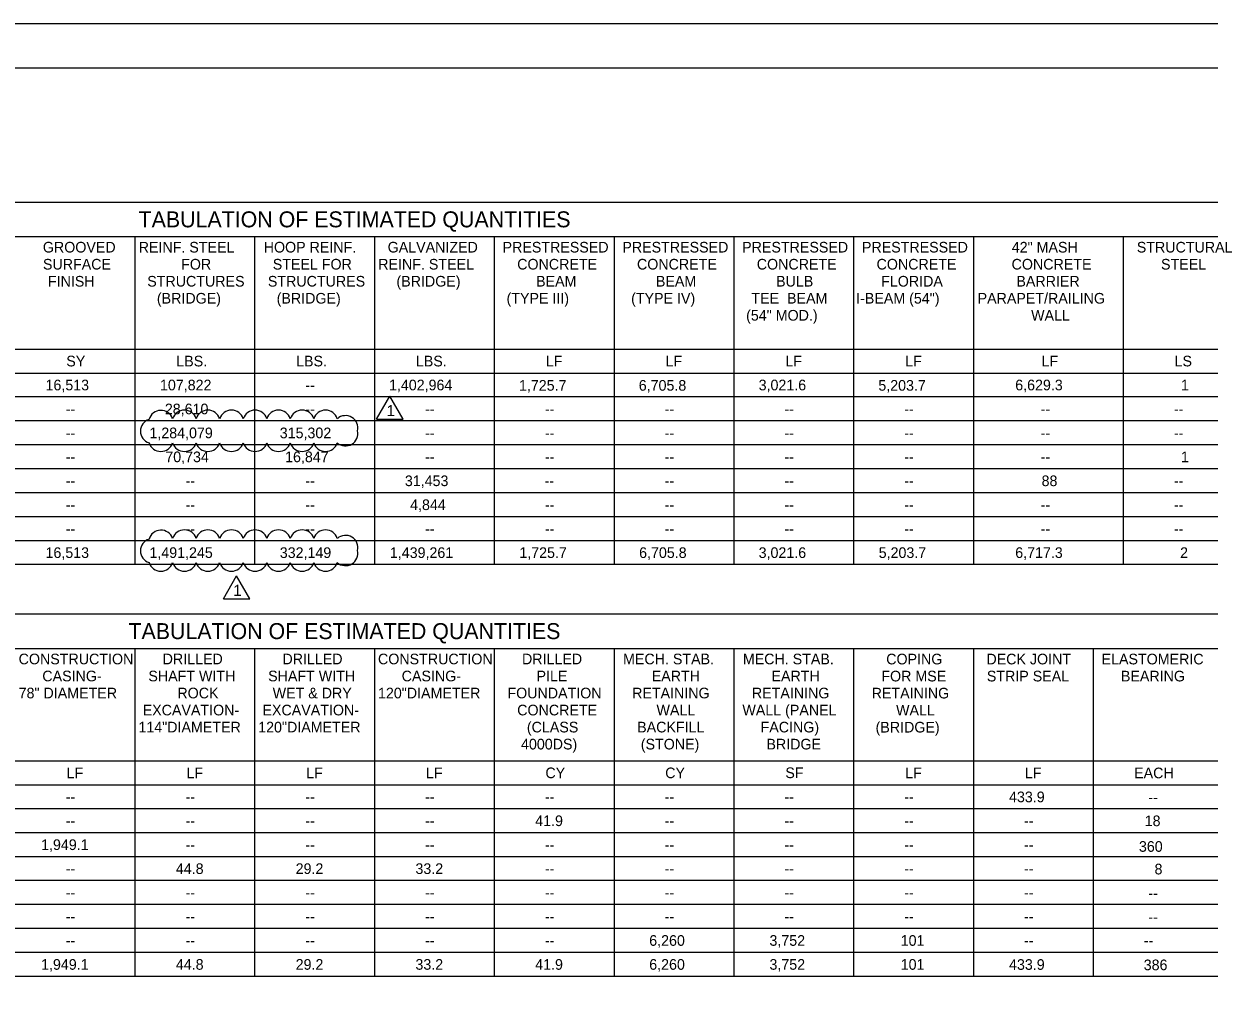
# Model space of a CAD drawing. Extents: x -125.5 to -89.4, y -5.1 to 16.9.
# Drawn here: x -111.65 to -98.29, y 5.93 to 16.93 of the extents above; entities that cross this region are included whole.
import ezdxf

# ---------------------------------------------------------------- set-up
doc = ezdxf.new("R2010")
doc.units = 0
for name, color, linetype in [('BR_BORDER LINES', 7, 'Continuous'), ('BR_TABLE LINES', 7, 'Continuous'), ('BR_TEXT', 7, 'Continuous'), ('Level 31', 7, 'Continuous')]:
    doc.layers.add(name, color=color, linetype=linetype)

msp = doc.modelspace()

# ---------------------------------------------------------------- linework, layer by layer
at = {"layer": 'BR_BORDER LINES'}
msp.add_line((-90.033, 16.434), (-123.699, 16.434), dxfattribs=at)
at = {"layer": 'BR_TABLE LINES'}
for p, q in [((-123.551, 14.923), (-90.138, 14.923)), ((-123.551, 14.533), (-90.138, 14.533)), ((-110.401, 14.533), (-110.401, 10.835)), ((-109.051, 14.533), (-109.051, 10.835)), ((-107.701, 14.533), (-107.701, 10.835)), ((-106.351, 14.533), (-106.351, 10.835)), ((-105.001, 14.533), (-105.001, 10.835)), ((-103.651, 14.533), (-103.651, 10.835)), ((-102.301, 14.533), (-102.301, 10.835)), ((-100.951, 14.533), (-100.951, 10.835)), ((-99.261, 14.533), (-99.261, 10.835)), ((-123.551, 13.265), (-90.138, 13.265)), ((-123.551, 12.995), (-90.138, 12.995)), ((-90.138, 12.725), (-123.551, 12.725)), ((-90.138, 12.455), (-123.551, 12.455)), ((-90.138, 12.185), (-123.551, 12.185)), ((-90.138, 11.915), (-123.551, 11.915)), ((-90.138, 11.645), (-123.551, 11.645)), ((-90.138, 11.375), (-123.551, 11.375)), ((-90.138, 11.105), (-123.551, 11.105)), ((-90.138, 10.835), (-123.551, 10.835)), ((-123.551, 10.28), (-91.389, 10.28)), ((-123.551, 9.89), (-91.389, 9.89)), ((-110.401, 9.89), (-110.401, 6.192)), ((-109.051, 9.89), (-109.051, 6.192)), ((-107.701, 9.89), (-107.701, 6.192)), ((-106.351, 9.89), (-106.351, 6.192)), ((-105.001, 9.89), (-105.001, 6.192)), ((-103.651, 9.89), (-103.651, 6.192)), ((-102.301, 9.889), (-102.301, 6.192)), ((-100.951, 9.889), (-100.951, 6.192)), ((-99.601, 9.889), (-99.601, 6.192)), ((-123.551, 8.622), (-91.389, 8.622)), ((-123.551, 8.352), (-91.389, 8.352)), ((-91.389, 8.082), (-123.551, 8.082)), ((-91.389, 7.812), (-123.551, 7.812)), ((-91.389, 7.542), (-123.551, 7.542)), ((-91.389, 7.272), (-123.551, 7.272)), ((-91.389, 7.002), (-123.551, 7.002)), ((-91.389, 6.732), (-123.551, 6.732)), ((-91.389, 6.462), (-123.551, 6.462)), ((-91.389, 6.192), (-123.551, 6.192))]:
    msp.add_line(p, q, dxfattribs=at)
at = {"layer": 'BR_TEXT'}
for p, q in [((-107.676, 12.475), (-107.526, 12.735)), ((-107.376, 12.475), (-107.526, 12.735)), ((-107.676, 12.475), (-107.376, 12.475)), ((-109.404, 10.449), (-109.254, 10.709)), ((-109.104, 10.449), (-109.254, 10.709)), ((-109.404, 10.449), (-109.104, 10.449))]:
    msp.add_line(p, q, dxfattribs=at)
for centre, start, end in [((-110.107, 12.435), 19.0694, 164.0694), ((-109.843, 12.438), 17.5, 162.5), ((-109.578, 12.438), 17.5, 162.5), ((-109.312, 12.438), 17.5, 162.5), ((-109.047, 12.438), 17.5, 162.5), ((-108.782, 12.438), 17.5, 162.5), ((-108.517, 12.438), 17.5, 162.5), ((-108.252, 12.438), 17.5, 162.5), ((-110.199, 12.34), 107.5, 252.5), ((-108.027, 12.376), 346.5605, 131.5605), ((-108.027, 12.312), 228.3256, 13.3256), ((-110.108, 12.25), 197.5, 342.5), ((-109.843, 12.25), 197.5, 342.5), ((-109.578, 12.25), 197.5, 342.5), ((-109.313, 12.25), 197.5, 342.5), ((-109.047, 12.25), 197.5, 342.5), ((-108.782, 12.25), 197.5, 342.5), ((-108.517, 12.25), 197.5, 342.5), ((-108.252, 12.25), 197.5, 342.5), ((-109.843, 11.088), 17.5, 162.5), ((-109.578, 11.088), 17.5, 162.5), ((-109.312, 11.088), 17.5, 162.5), ((-109.047, 11.088), 17.5, 162.5), ((-108.782, 11.088), 17.5, 162.5), ((-108.517, 11.088), 17.5, 162.5), ((-108.252, 11.088), 17.5, 162.5), ((-110.199, 10.99), 107.5, 252.5), ((-110.107, 11.085), 19.0694, 164.0694), ((-108.027, 11.026), 346.5605, 131.5605), ((-108.027, 10.962), 228.3256, 13.3256), ((-110.108, 10.9), 197.5, 342.5), ((-109.843, 10.9), 197.5, 342.5), ((-109.578, 10.9), 197.5, 342.5), ((-109.313, 10.9), 197.5, 342.5), ((-109.047, 10.9), 197.5, 342.5), ((-108.782, 10.9), 197.5, 342.5), ((-108.517, 10.9), 197.5, 342.5), ((-108.252, 10.9), 197.5, 342.5)]:
    msp.add_arc(centre, 0.139, start, end, dxfattribs=at)
at = {"layer": 'Level 31'}
msp.add_lwpolyline([(-125.533, -5.066), (-89.533, -5.066), (-89.533, 16.934), (-125.533, 16.934)], close=True, dxfattribs=at)

# ---------------------------------------------------------------- texts
at = {"layer": 'BR_TEXT'}
for s, height, p in [('TABULATION OF ESTIMATED QUANTITIES', 0.18, (-110.359, 14.638)), ('GROOVED ', 0.12, (-111.438, 14.354)), ('REINF. STEEL', 0.12, (-110.358, 14.354)), ('HOOP REINF. ', 0.12, (-108.949, 14.354)), ('GALVANIZED ', 0.12, (-107.552, 14.354)), ('PRESTRESSED ', 0.12, (-106.257, 14.354)), ('PRESTRESSED ', 0.12, (-104.907, 14.354)), ('PRESTRESSED ', 0.12, (-103.557, 14.354)), ('PRESTRESSED ', 0.12, (-102.207, 14.354)), ('42" MASH ', 0.12, (-100.518, 14.354)), ('STRUCTURAL ', 0.12, (-99.109, 14.354)), ('SURFACE ', 0.12, (-111.437, 14.162)), (' FOR', 0.12, (-109.924, 14.162)), ('STEEL FOR ', 0.12, (-108.847, 14.162)), ('REINF. STEEL ', 0.12, (-107.658, 14.162)), ('CONCRETE ', 0.12, (-106.092, 14.162)), ('CONCRETE ', 0.12, (-104.742, 14.162)), ('CONCRETE ', 0.12, (-103.392, 14.162)), ('CONCRETE', 0.12, (-102.042, 14.162)), ('CONCRETE ', 0.12, (-100.52, 14.162)), ('STEEL', 0.12, (-98.836, 14.162)), ('FINISH', 0.12, (-111.381, 13.97)), (' STRUCTURES ', 0.12, (-110.306, 13.97)), ('STRUCTURES ', 0.12, (-108.902, 13.97)), ('(BRIDGE)', 0.12, (-107.453, 13.97)), ('BEAM ', 0.12, (-105.879, 13.97)), ('BEAM ', 0.12, (-104.529, 13.97)), ('BULB ', 0.12, (-103.174, 13.97)), ('FLORIDA', 0.12, (-101.99, 13.97)), ('BARRIER ', 0.12, (-100.466, 13.97)), ('(BRIDGE)', 0.12, (-110.153, 13.778)), ('(BRIDGE)', 0.12, (-108.803, 13.778)), ('(TYPE III)', 0.12, (-106.212, 13.778)), ('(TYPE IV)', 0.12, (-104.808, 13.778)), ('TEE  BEAM ', 0.12, (-103.452, 13.778)), ('I-BEAM (54")', 0.12, (-102.272, 13.778)), ('PARAPET/RAILING ', 0.12, (-100.903, 13.778)), ('(54" MOD.)', 0.12, (-103.512, 13.586)), ('WALL', 0.12, (-100.3, 13.586)), ('SY', 0.12, (-111.174, 13.07)), ('LBS.', 0.12, (-109.934, 13.07)), ('LBS.', 0.12, (-108.584, 13.07)), ('LBS.', 0.12, (-107.234, 13.07)), ('LF', 0.12, (-105.77, 13.07)), ('LF', 0.12, (-104.42, 13.07)), ('LF', 0.12, (-103.07, 13.07)), ('LF', 0.12, (-101.72, 13.07)), ('LF', 0.12, (-100.182, 13.07)), ('LS', 0.12, (-98.683, 13.07)), ('16,513', 0.12, (-111.408, 12.8)), ('107,822', 0.12, (-110.118, 12.8)), ('--', 0.12, (-108.48, 12.8)), ('1,402,964', 0.12, (-107.537, 12.8)), ('1,725.7', 0.12, (-106.072, 12.796)), ('6,705.8', 0.12, (-104.722, 12.796)), ('3,021.6', 0.12, (-103.371, 12.8)), ('5,203.7', 0.12, (-102.022, 12.796)), ('6,629.3', 0.12, (-100.479, 12.8)), ('1', 0.12, (-98.611, 12.8)), ('--', 0.12, (-111.18, 12.53)), ('28,610', 0.12, (-110.063, 12.53)), ('--', 0.12, (-108.48, 12.53)), ('--', 0.12, (-107.13, 12.53)), ('--', 0.12, (-105.78, 12.53)), ('--', 0.12, (-104.43, 12.53)), ('--', 0.12, (-103.08, 12.53)), ('--', 0.12, (-101.73, 12.53)), ('--', 0.12, (-100.192, 12.53)), ('--', 0.12, (-98.69, 12.53)), ('--', 0.12, (-111.18, 12.26)), ('1,284,079', 0.12, (-110.237, 12.26)), ('315,302', 0.12, (-108.768, 12.26)), ('--', 0.12, (-107.13, 12.26)), ('--', 0.12, (-105.78, 12.26)), ('--', 0.12, (-104.43, 12.26)), ('--', 0.12, (-103.08, 12.26)), ('--', 0.12, (-101.73, 12.26)), ('--', 0.12, (-100.192, 12.26)), ('--', 0.12, (-98.69, 12.26)), ('--', 0.12, (-111.18, 11.99)), ('70,734', 0.12, (-110.058, 11.99)), ('16,847', 0.12, (-108.708, 11.99)), ('--', 0.12, (-107.13, 11.99)), ('--', 0.12, (-105.78, 11.99)), ('--', 0.12, (-104.43, 11.99)), ('--', 0.12, (-103.08, 11.99)), ('--', 0.12, (-101.73, 11.99)), ('--', 0.12, (-100.192, 11.99)), ('1', 0.12, (-98.611, 11.99)), ('--', 0.12, (-111.18, 11.72)), ('--', 0.12, (-109.83, 11.72)), ('--', 0.12, (-108.48, 11.72)), ('31,453', 0.12, (-107.358, 11.72)), ('--', 0.12, (-105.783, 11.721)), ('--', 0.12, (-104.43, 11.72)), ('--', 0.12, (-103.08, 11.72)), ('--', 0.12, (-101.73, 11.72)), ('88', 0.12, (-100.182, 11.72)), ('--', 0.12, (-98.69, 11.72)), ('--', 0.12, (-111.18, 11.45)), ('--', 0.12, (-109.83, 11.45)), ('--', 0.12, (-108.48, 11.45)), ('4,844', 0.12, (-107.299, 11.45)), ('--', 0.12, (-105.78, 11.45)), ('--', 0.12, (-104.43, 11.45)), ('--', 0.12, (-103.08, 11.45)), ('--', 0.12, (-101.73, 11.45)), ('--', 0.12, (-100.192, 11.45)), ('--', 0.12, (-98.69, 11.45)), ('--', 0.12, (-111.18, 11.18)), ('--', 0.12, (-109.83, 11.18)), ('--', 0.12, (-108.48, 11.18)), ('--', 0.12, (-107.13, 11.18)), ('--', 0.12, (-105.78, 11.18)), ('--', 0.12, (-104.43, 11.18)), ('--', 0.12, (-103.08, 11.18)), ('--', 0.12, (-101.73, 11.18)), ('--', 0.12, (-100.192, 11.18)), ('--', 0.12, (-98.69, 11.18)), ('16,513', 0.12, (-111.408, 10.91)), ('1,491,245', 0.12, (-110.237, 10.91)), ('332,149', 0.12, (-108.768, 10.91)), ('1,439,261', 0.12, (-107.527, 10.91)), ('1,725.7', 0.12, (-106.068, 10.91)), ('6,705.8', 0.12, (-104.718, 10.91)), ('3,021.6', 0.12, (-103.371, 10.91)), ('5,203.7', 0.12, (-102.018, 10.91)), ('6,717.3', 0.12, (-100.479, 10.91)), ('2', 0.12, (-98.621, 10.91)), ('TABULATION OF ESTIMATED QUANTITIES', 0.18, (-110.473, 9.995)), ('CONSTRUCTION ', 0.12, (-111.711, 9.711)), ('DRILLED ', 0.12, (-110.088, 9.711)), ('DRILLED ', 0.12, (-108.738, 9.711)), ('CONSTRUCTION ', 0.12, (-107.661, 9.711)), ('DRILLED ', 0.12, (-106.038, 9.711)), ('MECH. STAB. ', 0.12, (-104.899, 9.711)), ('MECH. STAB. ', 0.12, (-103.549, 9.711)), ('COPING ', 0.12, (-101.933, 9.71)), ('DECK JOINT ', 0.12, (-100.804, 9.71)), ('ELASTOMERIC ', 0.12, (-99.506, 9.71)), ('CASING- ', 0.12, (-111.444, 9.519)), ('SHAFT WITH ', 0.12, (-110.249, 9.519)), ('SHAFT WITH ', 0.12, (-108.899, 9.519)), ('CASING- ', 0.12, (-107.394, 9.519)), ('PILE ', 0.12, (-105.874, 9.519)), ('EARTH ', 0.12, (-104.576, 9.519)), ('EARTH ', 0.12, (-103.226, 9.519)), ('FOR MSE ', 0.12, (-101.988, 9.518)), ('STRIP SEAL', 0.12, (-100.799, 9.518)), ('BEARING', 0.12, (-99.288, 9.518)), ('78" DIAMETER', 0.12, (-111.711, 9.327)), ('ROCK ', 0.12, (-109.922, 9.327)), ('WET & DRY ', 0.12, (-108.848, 9.327)), ('120"DIAMETER', 0.12, (-107.661, 9.327)), ('FOUNDATION ', 0.12, (-106.202, 9.327)), ('RETAINING ', 0.12, (-104.797, 9.327)), ('RETAINING ', 0.12, (-103.447, 9.327)), ('RETAINING ', 0.12, (-102.097, 9.326)), ('EXCAVATION- ', 0.12, (-110.313, 9.135)), ('EXCAVATION- ', 0.12, (-108.963, 9.135)), ('CONCRETE ', 0.12, (-106.092, 9.135)), ('WALL ', 0.12, (-104.522, 9.135)), ('WALL (PANEL ', 0.12, (-103.554, 9.135)), ('WALL ', 0.12, (-101.822, 9.134)), ('114"DIAMETER', 0.12, (-110.361, 8.943)), ('120"DIAMETER', 0.12, (-109.011, 8.943)), ('(CLASS ', 0.12, (-105.983, 8.943)), ('BACKFILL ', 0.12, (-104.74, 8.943)), ('FACING) ', 0.12, (-103.349, 8.943)), ('(BRIDGE)', 0.12, (-102.053, 8.942)), ('4000DS)', 0.12, (-106.049, 8.751)), ('(STONE)', 0.12, (-104.699, 8.751)), ('BRIDGE', 0.12, (-103.283, 8.751)), ('LF', 0.12, (-111.17, 8.427)), ('LF', 0.12, (-109.82, 8.427)), ('LF', 0.12, (-108.47, 8.427)), ('LF', 0.12, (-107.12, 8.427)), ('CY', 0.12, (-105.774, 8.427)), ('CY', 0.12, (-104.424, 8.427)), ('SF', 0.12, (-103.07, 8.428)), ('LF', 0.12, (-101.72, 8.426)), ('LF', 0.12, (-100.37, 8.426)), ('EACH', 0.12, (-99.139, 8.426)), ('--', 0.12, (-111.18, 8.157)), ('--', 0.12, (-109.83, 8.157)), ('--', 0.12, (-108.48, 8.157)), ('--', 0.12, (-107.13, 8.157)), ('--', 0.12, (-105.78, 8.157)), ('--', 0.12, (-104.43, 8.157)), ('--', 0.12, (-103.08, 8.157)), ('--', 0.12, (-101.73, 8.157)), ('433.9', 0.12, (-100.549, 8.156)), ('--', 0.12, (-98.979, 8.152)), ('--', 0.12, (-111.18, 7.887)), ('--', 0.12, (-109.83, 7.887)), ('--', 0.12, (-108.48, 7.887)), ('--', 0.12, (-107.13, 7.887)), ('41.9', 0.12, (-105.889, 7.887)), ('--', 0.12, (-104.43, 7.887)), ('--', 0.12, (-103.08, 7.887)), ('--', 0.12, (-101.73, 7.887)), ('--', 0.12, (-100.38, 7.887)), ('18', 0.12, (-99.02, 7.886)), ('1,949.1', 0.12, (-111.458, 7.617)), ('--', 0.12, (-109.83, 7.617)), ('--', 0.12, (-108.48, 7.617)), ('--', 0.12, (-107.13, 7.617)), ('--', 0.12, (-105.78, 7.617)), ('--', 0.12, (-104.43, 7.617)), ('--', 0.12, (-103.08, 7.617)), ('--', 0.12, (-101.73, 7.617)), ('--', 0.12, (-100.38, 7.617)), ('360', 0.12, (-99.085, 7.597)), ('--', 0.12, (-111.18, 7.347)), ('44.8', 0.12, (-109.939, 7.347)), ('29.2', 0.12, (-108.589, 7.347)), ('33.2', 0.12, (-107.239, 7.347)), ('--', 0.12, (-105.78, 7.347)), ('--', 0.12, (-104.43, 7.347)), ('--', 0.12, (-103.08, 7.347)), ('--', 0.12, (-101.73, 7.347)), ('--', 0.12, (-100.38, 7.347)), ('8', 0.12, (-98.909, 7.342)), ('--', 0.12, (-111.18, 7.077)), ('--', 0.12, (-109.83, 7.077)), ('--', 0.12, (-108.48, 7.077)), ('--', 0.12, (-107.13, 7.077)), ('--', 0.12, (-105.78, 7.077)), ('--', 0.12, (-104.43, 7.077)), ('--', 0.12, (-103.08, 7.077)), ('--', 0.12, (-101.73, 7.077)), ('--', 0.12, (-100.38, 7.077)), ('--', 0.12, (-98.979, 7.072)), ('--', 0.12, (-111.18, 6.807)), ('--', 0.12, (-109.83, 6.807)), ('--', 0.12, (-108.48, 6.807)), ('--', 0.12, (-107.13, 6.807)), ('--', 0.12, (-105.78, 6.807)), ('--', 0.12, (-104.43, 6.807)), ('--', 0.12, (-103.08, 6.807)), ('--', 0.12, (-101.73, 6.807)), ('--', 0.12, (-100.38, 6.807)), ('--', 0.12, (-98.979, 6.802)), ('--', 0.12, (-111.18, 6.537)), ('--', 0.12, (-109.83, 6.537)), ('--', 0.12, (-108.48, 6.537)), ('--', 0.12, (-107.13, 6.537)), ('--', 0.12, (-105.78, 6.537)), ('6,260', 0.12, (-104.604, 6.537)), ('3,752', 0.12, (-103.249, 6.537)), ('101', 0.12, (-101.77, 6.537)), ('--', 0.12, (-100.38, 6.537)), ('--', 0.12, (-99.03, 6.537)), ('1,949.1', 0.12, (-111.458, 6.267)), ('44.8', 0.12, (-109.939, 6.267)), ('29.2', 0.12, (-108.589, 6.267)), ('33.2', 0.12, (-107.239, 6.267)), ('41.9', 0.12, (-105.889, 6.267)), ('6,260', 0.12, (-104.604, 6.267)), ('3,752', 0.12, (-103.249, 6.267)), ('101', 0.12, (-101.77, 6.267)), ('433.9', 0.12, (-100.549, 6.266)), ('386', 0.12, (-99.031, 6.262))]:
    msp.add_text(s, height=height, dxfattribs=at).set_placement(p)
for p in [(-107.563, 12.509), (-109.291, 10.483)]:
    msp.add_text('1', height=0.125, rotation=360, dxfattribs=at).set_placement(p)

doc.saveas('drawing.dxf')
